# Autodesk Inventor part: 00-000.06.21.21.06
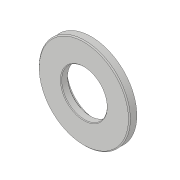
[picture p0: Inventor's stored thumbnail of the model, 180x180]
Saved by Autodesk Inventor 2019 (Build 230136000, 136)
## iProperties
Created: 2019-01
Part Number: 00-000.06.21.21.06
Material: Generic
Document SubType Name: Modeling
Designer: m.vorobev
Density: 1 g/cm^3
Appearance: Default
Author: m.vorobev
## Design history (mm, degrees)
sketch "Sketch1"
  geometry: L1 (0, 0)-(7.413, 0); L2 (7.413, 0)-(7.413, -7.837); L3 (7.413, -7.837)-(0, -7.837); L4 (0, -7.837)-(0, 0); L5 (-35, 11.5)-(-70, 11.5); L6 (-70, 11.5)-(-70, 0); L7 (-70, 0)-(-35, 0); L8 (-35, 0)-(-35, 11.5); L9 (-50, 0)-(-45, 0); L10 (-45, 0)-(-45, -7.5); L11 (-45, -7.5)-(-50, -7.5); L12 (-50, -7.5)-(-50, 0); L13 (-45, 0)-(-35, 0); L14 (-35, 0)-(-35, 0.5); L15 (-35, 0.5)-(-45, 0.5); L16 (-45, 0.5)-(-45, 0); 1 further point
  constraints: 32 end point, 8 parallel, 4 horizontal, 4 perpendicular, 2 point on line, 1 horizontal alignment, 1 midpoint
  dimensions: "d0" = 19 distance between parallel lines of L5 L11; "d1" = 140 diameter of L6 L4; "d2" = 100 diameter of L12 L4; "d3" = 90 diameter of L10 L4; "d4" = 7.5 distance of L11.end L9.start; "d5" = 0.5 distance of L15.end L9.end; "Ukn" = 70 diameter of L8 L4
revolve "Revolution1" sketch "Sketch1" stored, may be unused: angle "d7" = 90 deg
chamfer "Chamfer1" distance "d8" = 1; stored, may be unused: second distance "d9" = 2, angle "d10" = 45 deg
fillet "Fillet1" dims "d11" = 2
chamfer "Chamfer2" distance "d12" = 1.5; stored, may be unused: second distance "d13" = 2, angle "d14" = 45 deg
body "Solid1"
